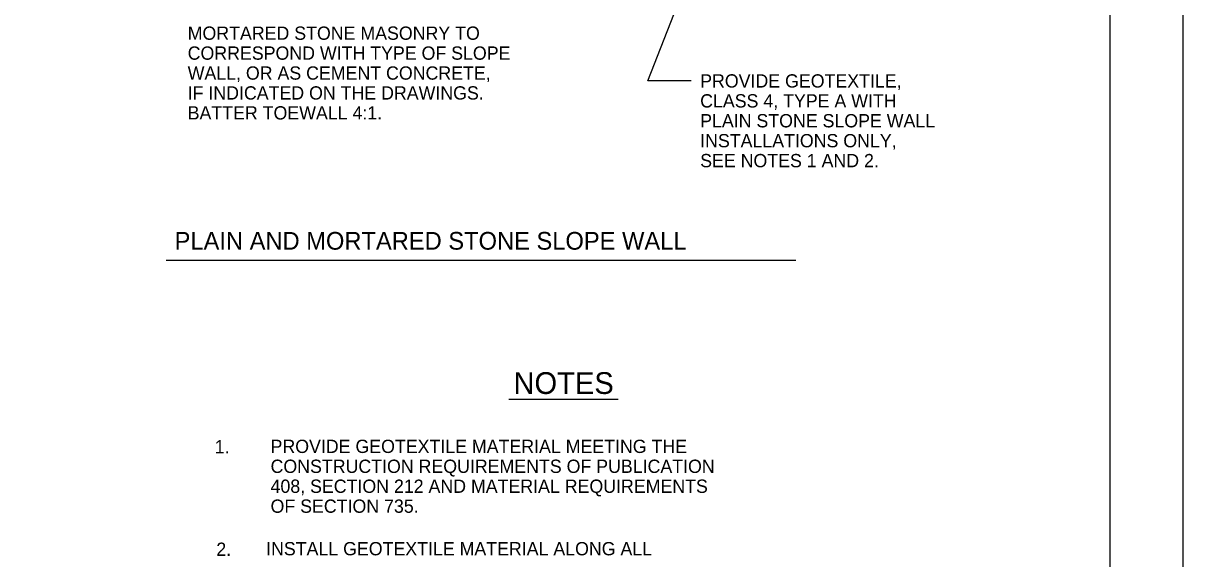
# Model space of a CAD drawing. Extents: x 5 to 910, y -47 to 547.
# Drawn here: x 606.1 to 845.7, y 249.8 to 360.5 of the extents above; entities that cross this region are included whole.
import ezdxf

# ---------------------------------------------------------------- set-up
doc = ezdxf.new("R2010")
doc.units = 0
for name, color, linetype in [('1', 7, 'Continuous'), ('2', 7, 'Continuous'), ('3', 7, 'Continuous'), ('PLT-BNDY', 7, 'Continuous')]:
    doc.layers.add(name, color=color, linetype=linetype)

msp = doc.modelspace()

# ---------------------------------------------------------------- linework, layer by layer
at = {"layer": '1'}
msp.add_line((729.03, 282.76), (706.44, 282.76), dxfattribs=at)
msp.add_lwpolyline([(830.72, -31.53), (830.72, 532.47), (44.72, 532.47), (44.72, -31.53), (830.72, -31.53), (830.72, -5.17), (630.72, -5.17), (630.72, 59.51), (830.72, 59.51), (830.72, 88.47), (630.72, 88.47), (630.72, -31.53), (709.52, -31.53), (709.52, -5.17), (709.52, -31.53), (786.52, -31.53), (786.52, -5.17), (786.52, -17.48), (830.72, -17.48)], dxfattribs=at)
at = {"layer": '2'}
for p, q in [((744.09, 348.64), (735.14, 348.64)), ((765.77, 311.46), (635.61, 311.46))]:
    msp.add_line(p, q, dxfattribs=at)
at = {"layer": '3'}
msp.add_line((735.14, 348.64), (748.69, 383.3), dxfattribs=at)
at = {"layer": 'PLT-BNDY'}
msp.add_lwpolyline([(4.72, 547.47), (845.72, 547.47), (845.72, -46.53), (4.72, -46.53)], close=True, dxfattribs=at)

# ---------------------------------------------------------------- texts
at = {"layer": '2'}
for s, height, p in [('MORTARED STONE MASONRY TO', 2.7454, (640.05, 357.1)), ('CORRESPOND WITH TYPE OF SLOPE', 2.7454, (640.05, 352.98)), ('WALL, OR AS CEMENT CONCRETE,', 2.7454, (640.05, 348.86)), ('PROVIDE GEOTEXTILE,', 2.7454, (745.97, 347.23)), ('IF INDICATED ON THE DRAWINGS.', 2.7454, (640.05, 344.75)), ('CLASS 4, TYPE A WITH', 2.7454, (745.97, 343.11)), ('BATTER TOEWALL 4:1.', 2.7454, (640.05, 340.63)), ('PLAIN STONE SLOPE WALL', 2.7454, (745.97, 339)), ('INSTALLATIONS ONLY,', 2.7454, (745.97, 334.88)), ('SEE NOTES 1 AND 2.', 2.7454, (745.97, 330.76)), ('1.', 2.745, (645.65, 271.64)), ('PROVIDE GEOTEXTILE MATERIAL MEETING THE', 2.7454, (657.18, 271.71)), ('CONSTRUCTION REQUIREMENTS OF PUBLICATION', 2.7454, (657.18, 267.59)), ('408, SECTION 212 AND MATERIAL REQUIREMENTS', 2.7454, (657.18, 263.47)), ('OF SECTION 735.', 2.7454, (657.18, 259.35)), ('2.', 2.745, (645.97, 250.45)), ('INSTALL GEOTEXTILE MATERIAL ALONG ALL', 2.7454, (656.26, 250.56))]:
    msp.add_text(s, height=height, dxfattribs=at).set_placement(p)
at = {"layer": '3'}
for s, height, p in [('PLAIN AND MORTARED STONE SLOPE WALL', 3.6603, (637.35, 313.73)), ('NOTES', 4.5, (707.38, 283.91))]:
    msp.add_text(s, height=height, dxfattribs=at).set_placement(p)

doc.saveas('drawing.dxf')
